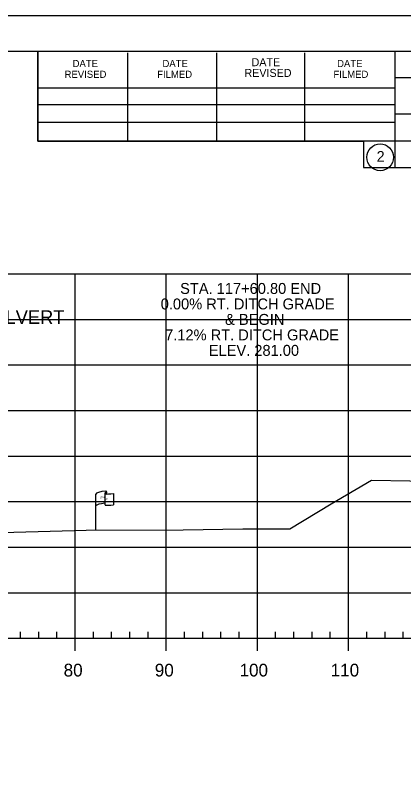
# Model space of a CAD drawing. Extents: x 1370843 to 1371177, y 380307 to 382654.
# Drawn here: x 1371087.2 to 1371129.7, y 381715.3 to 381800.8 of the extents above; entities that cross this region are included whole.
import ezdxf

# ---------------------------------------------------------------- set-up
doc = ezdxf.new("R2010")
doc.units = 0
for name, color, linetype in [('R_Axis', 7, 'Continuous'), ('R_Axis Annot', 7, 'Continuous'), ('R_Border', 7, 'Continuous'), ('R_Exist Surface', 7, 'Continuous'), ('R_Grid', 7, 'Continuous'), ('R_No Plot', 7, 'Continuous'), ('R_ROW', 7, 'Continuous'), ('R_Water Annot', 7, 'Continuous')]:
    doc.layers.add(name, color=color, linetype=linetype)

msp = doc.modelspace()

# ---------------------------------------------------------------- linework, layer by layer
at = {"layer": 'R_Axis'}
for p, q in [((1371087.709, 381732.476), (1371087.709, 381733.176)), ((1371089.709, 381732.476), (1371089.709, 381733.176)), ((1371091.709, 381732.476), (1371091.709, 381733.176)), ((1371095.709, 381732.476), (1371095.709, 381733.176)), ((1371097.709, 381732.476), (1371097.709, 381733.176)), ((1371099.709, 381732.476), (1371099.709, 381733.176)), ((1371101.709, 381732.476), (1371101.709, 381733.176)), ((1371105.709, 381732.476), (1371105.709, 381733.176)), ((1371107.709, 381732.476), (1371107.709, 381733.176)), ((1371109.709, 381732.476), (1371109.709, 381733.176)), ((1371111.709, 381732.476), (1371111.709, 381733.176)), ((1371115.709, 381732.476), (1371115.709, 381733.176)), ((1371117.709, 381732.476), (1371117.709, 381733.176)), ((1371119.709, 381732.476), (1371119.709, 381733.176)), ((1371121.709, 381732.476), (1371121.709, 381733.176)), ((1371125.709, 381732.476), (1371125.709, 381733.176)), ((1371127.709, 381732.476), (1371127.709, 381733.176)), ((1371129.709, 381732.476), (1371129.709, 381733.176)), ((1370868.709, 381732.476), (1371158.709, 381732.476)), ((1371093.709, 381731.076), (1371093.709, 381732.476)), ((1371103.709, 381731.076), (1371103.709, 381732.476)), ((1371113.709, 381731.076), (1371113.709, 381732.476)), ((1371123.709, 381731.076), (1371123.709, 381732.476))]:
    msp.add_line(p, q, dxfattribs=at)
at = {"layer": 'R_Border'}
for p, q in [((1370855.709, 381796.936), (1371171.889, 381796.936)), ((1371089.629, 381787.056), (1371089.629, 381796.936)), ((1371099.489, 381787.056), (1371099.489, 381796.736)), ((1371109.249, 381787.056), (1371109.249, 381796.736)), ((1371118.929, 381787.056), (1371118.929, 381796.736)), ((1371128.789, 381796.936), (1371128.789, 381784.136)), ((1371171.889, 381793.996), (1371128.789, 381793.996)), ((1371089.629, 381792.916), (1371128.789, 381792.916)), ((1371089.629, 381791.056), (1371128.789, 381791.056)), ((1371171.889, 381789.996), (1371128.789, 381789.996)), ((1371089.629, 381787.056), (1371089.629, 381789.116)), ((1371089.629, 381789.116), (1371128.789, 381789.116)), ((1371171.889, 381787.056), (1371089.629, 381787.056)), ((1371128.789, 381784.136), (1371171.889, 381784.136))]:
    msp.add_line(p, q, dxfattribs=at)
msp.add_circle((1371127.176, 381785.272), 1.467, dxfattribs=at)
at = {"layer": 'R_Exist Surface'}
msp.add_lwpolyline([(1371082.984, 381744.028), (1371094.92, 381744.343), (1371105.544, 381744.371), (1371112.113, 381744.479), (1371117.256, 381744.501), (1371121.786, 381747.246), (1371126.243, 381749.812), (1371130.437, 381749.748), (1371131.72, 381749.721), (1371149.166, 381749.431), (1371156.796, 381749.259), (1371158.709, 381749.214)], dxfattribs=at)
at = {"layer": 'R_Grid'}
for p, q in [((1370868.709, 381772.476), (1371158.709, 381772.476)), ((1371093.709, 381732.476), (1371093.709, 381772.476)), ((1371103.709, 381732.476), (1371103.709, 381772.476)), ((1371113.709, 381732.476), (1371113.709, 381772.476)), ((1371123.709, 381732.476), (1371123.709, 381772.476)), ((1370868.709, 381767.476), (1371158.709, 381767.476)), ((1370868.709, 381762.476), (1371158.709, 381762.476)), ((1370868.709, 381757.476), (1371158.709, 381757.476)), ((1370868.709, 381752.476), (1371158.709, 381752.476)), ((1370868.709, 381747.476), (1371158.709, 381747.476)), ((1370868.709, 381742.476), (1371158.709, 381742.476)), ((1370868.709, 381737.476), (1371158.709, 381737.476)), ((1370868.709, 381732.476), (1371158.709, 381732.476))]:
    msp.add_line(p, q, dxfattribs=at)
at = {"layer": 'R_No Plot'}
msp.add_line((1370843.308, 381800.831), (1371176.642, 381800.831), dxfattribs=at)
for points in [[(1370843.302, 381800.831), (1371176.642, 381800.831), (1371176.642, 381587.493), (1370843.302, 381587.493)], [(1371089.629, 381796.936), (1371089.629, 381787.056), (1371125.361, 381787.056), (1371125.361, 381784.136), (1371148.561, 381784.136), (1371148.561, 381759.804), (1371171.889, 381759.804), (1371171.889, 381591.476), (1370855.709, 381591.476), (1370855.709, 381796.936)]]:
    msp.add_lwpolyline(points, close=True, dxfattribs=at)
at = {"layer": 'R_ROW'}
for p, q in [((1371095.987, 381744.346), (1371095.987, 381748.296)), ((1371096.982, 381748.391), (1371096.982, 381748.377)), ((1371096.982, 381748.377), (1371096.982, 381747.151)), ((1371097.15, 381748.547), (1371097.15, 381748.307)), ((1371097.917, 381748.353), (1371097.917, 381747.113))]:
    msp.add_line(p, q, dxfattribs=at)
for centre, radius, start, end in [((1371097.06, 381748.391), 0.078, 88.6458, 274.28284), ((1371097.071, 381748.547), 0.0783, 263.07118, 93.95638), ((1371097.061, 381747.151), 0.0783, 180, 273.95638)]:
    msp.add_arc(centre, radius, start, end, dxfattribs=at)
for centre, major_axis, ratio, start_param, end_param in [((1371097.569, 381748.34), (-1.582, -0.043), 0.19887, 5.030368, 6.283185), ((1371098.276, 381748.455), (-1.227, -0.134), 0.052933, 0.159456, 1.268315), ((1371097.563, 381747.022), (-1.582, -0.043), 0.19887, 5.083035, 6.194897), ((1371098.276, 381747.215), (-1.227, -0.134), 0.052933, 0.159456, 1.268315)]:
    msp.add_ellipse(centre, major_axis=major_axis, ratio=ratio, start_param=start_param, end_param=end_param, dxfattribs=at)

# ---------------------------------------------------------------- texts
at = {"layer": 'R_Axis Annot'}
for s, p in [('80', (1371092.448, 381728.276)), ('90', (1371102.448, 381728.276)), ('100', (1371111.748, 381728.276)), ('110', (1371121.748, 381728.276))]:
    msp.add_text(s, height=1.4, dxfattribs=at).set_placement(p)
at = {"layer": 'R_Border'}
for s, height, p in [('DATE', 0.8792, (1371113.069, 381795.276)), ('DATE', 0.7819, (1371093.429, 381795.176)), ('DATE', 0.7819, (1371103.289, 381795.176)), ('DATE', 0.7819, (1371122.449, 381795.176)), ('REVISED', 0.7819, (1371092.549, 381793.996)), ('FILMED', 0.7819, (1371102.709, 381793.996)), ('REVISED', 0.8792, (1371112.289, 381794.096)), ('FILMED', 0.7819, (1371122.049, 381793.996)), ('2', 1.172, (1371126.793, 381784.785))]:
    msp.add_text(s, height=height, rotation=360, dxfattribs=at).set_placement(p)
at = {"layer": 'R_ROW'}
for s, height, rotation, p in [('DWB 11-9-07', 0.001, 90, (1371097.149, 381748.307)), ('R ', 0.2, 9.98841, (1371096.506, 381747.798)), (' O', 0.2, 9.98841, (1371096.652, 381747.843)), ('W', 0.2, 351.17882, (1371096.982, 381747.674)), ('DWB 11-9-07', 0.001, 5.07169, (1371097.907, 381747.113)), ('DWB 11-9-07', 0.001, 90, (1371095.986, 381744.346))]:
    msp.add_text(s, height=height, rotation=rotation, dxfattribs=at).set_placement(p)
at = {"layer": 'R_Water Annot'}
for s, height, p in [('STA. 117+60.80 END', 1.2, (1371105.229, 381770.276)), ('0.00% RT. DITCH GRADE', 1.2, (1371103.098, 381768.576)), ("QUINT. 1 1' X 9' X 62' R.C. BOX CULVERT", 1.5, (1371053.709, 381766.976)), ('& BEGIN', 1.2, (1371110.161, 381766.876)), ('7.12% RT. DITCH GRADE', 1.2, (1371103.58, 381765.176)), ('ELEV. 281.00', 1.2, (1371108.375, 381763.476))]:
    msp.add_text(s, height=height, dxfattribs=at).set_placement(p)

doc.saveas('drawing.dxf')
